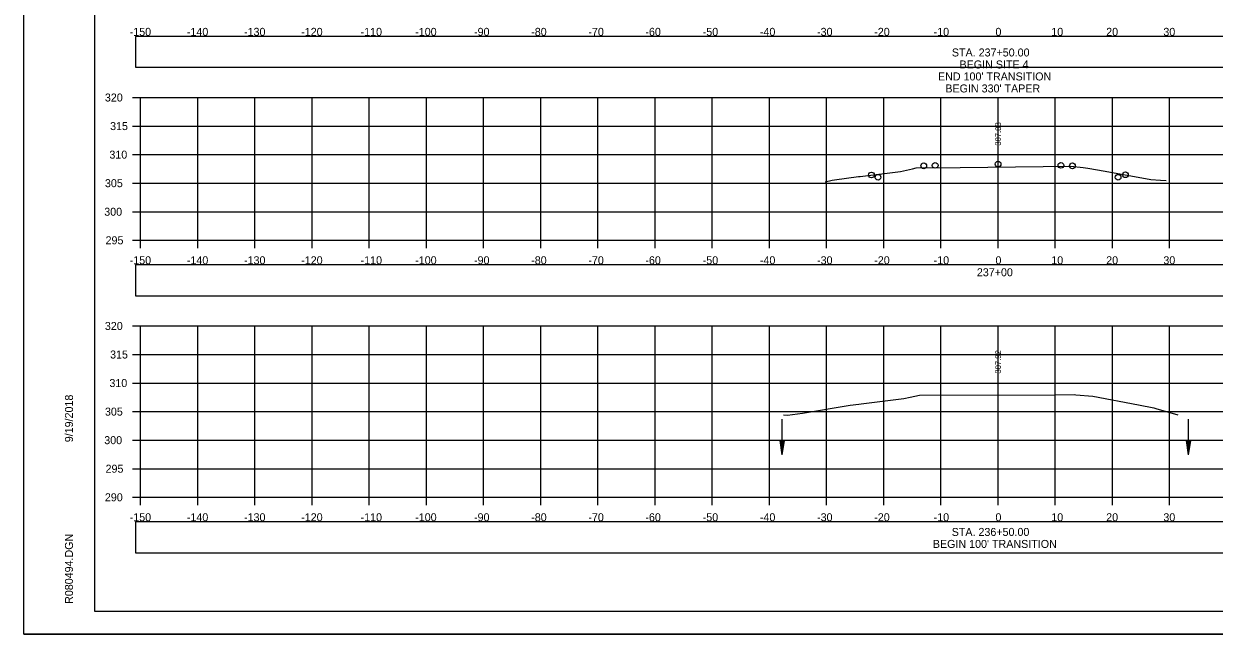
# Model space of a CAD drawing. Extents: x 1376273 to 1384221, y 378927 to 384592.
# Drawn here: x 1380387.4 to 1380595.6, y 379685.2 to 379792.1 of the extents above; entities that cross this region are included whole.
import ezdxf

# ---------------------------------------------------------------- set-up
doc = ezdxf.new("R2010")
doc.units = 0
for name, color, linetype in [('R_Axis', 7, 'Continuous'), ('R_Axis Annot', 7, 'Continuous'), ('R_Border', 7, 'Continuous'), ('R_Exist Surface', 7, 'Continuous'), ('R_Grid', 7, 'Continuous'), ('R_No Plot', 7, 'Continuous'), ('R_Water', 7, 'Continuous'), ('R_Xsect Elev', 7, 'Continuous')]:
    doc.layers.add(name, color=color, linetype=linetype)

msp = doc.modelspace()

# ---------------------------------------------------------------- linework, layer by layer
at = {"layer": 'R_Axis'}
for p, q in [((1380406.44, 379779.14), (1380407.84, 379779.14)), ((1380407.84, 379754.14), (1380407.84, 379779.14)), ((1380406.44, 379774.14), (1380407.84, 379774.14)), ((1380406.44, 379769.14), (1380407.84, 379769.14)), ((1380406.44, 379764.14), (1380407.84, 379764.14)), ((1380406.44, 379759.14), (1380407.84, 379759.14)), ((1380406.44, 379754.14), (1380407.84, 379754.14)), ((1380407.84, 379754.14), (1380707.84, 379754.14)), ((1380407.84, 379752.74), (1380407.84, 379754.14)), ((1380417.84, 379752.74), (1380417.84, 379754.14)), ((1380427.84, 379752.74), (1380427.84, 379754.14)), ((1380437.84, 379752.74), (1380437.84, 379754.14)), ((1380447.84, 379752.74), (1380447.84, 379754.14)), ((1380457.84, 379752.74), (1380457.84, 379754.14)), ((1380467.84, 379752.74), (1380467.84, 379754.14)), ((1380477.84, 379752.74), (1380477.84, 379754.14)), ((1380487.84, 379752.74), (1380487.84, 379754.14)), ((1380497.84, 379752.74), (1380497.84, 379754.14)), ((1380507.84, 379752.74), (1380507.84, 379754.14)), ((1380517.84, 379752.74), (1380517.84, 379754.14)), ((1380527.84, 379752.74), (1380527.84, 379754.14)), ((1380537.84, 379752.74), (1380537.84, 379754.14)), ((1380547.84, 379752.74), (1380547.84, 379754.14)), ((1380557.84, 379752.74), (1380557.84, 379754.14)), ((1380567.84, 379752.74), (1380567.84, 379754.14)), ((1380577.84, 379752.74), (1380577.84, 379754.14)), ((1380587.84, 379752.74), (1380587.84, 379754.14)), ((1380406.44, 379739.14), (1380407.84, 379739.14)), ((1380407.84, 379709.14), (1380407.84, 379739.14)), ((1380406.44, 379734.14), (1380407.84, 379734.14)), ((1380406.44, 379729.14), (1380407.84, 379729.14)), ((1380406.44, 379724.14), (1380407.84, 379724.14)), ((1380406.44, 379719.14), (1380407.84, 379719.14)), ((1380406.44, 379714.14), (1380407.84, 379714.14)), ((1380406.44, 379709.14), (1380407.84, 379709.14)), ((1380407.84, 379709.14), (1380707.84, 379709.14)), ((1380407.84, 379707.74), (1380407.84, 379709.14)), ((1380417.84, 379707.74), (1380417.84, 379709.14)), ((1380427.84, 379707.74), (1380427.84, 379709.14)), ((1380437.84, 379707.74), (1380437.84, 379709.14)), ((1380447.84, 379707.74), (1380447.84, 379709.14)), ((1380457.84, 379707.74), (1380457.84, 379709.14)), ((1380467.84, 379707.74), (1380467.84, 379709.14)), ((1380477.84, 379707.74), (1380477.84, 379709.14)), ((1380487.84, 379707.74), (1380487.84, 379709.14)), ((1380497.84, 379707.74), (1380497.84, 379709.14)), ((1380507.84, 379707.74), (1380507.84, 379709.14)), ((1380517.84, 379707.74), (1380517.84, 379709.14)), ((1380527.84, 379707.74), (1380527.84, 379709.14)), ((1380537.84, 379707.74), (1380537.84, 379709.14)), ((1380547.84, 379707.74), (1380547.84, 379709.14)), ((1380557.84, 379707.74), (1380557.84, 379709.14)), ((1380567.84, 379707.74), (1380567.84, 379709.14)), ((1380577.84, 379707.74), (1380577.84, 379709.14)), ((1380587.84, 379707.74), (1380587.84, 379709.14))]:
    msp.add_line(p, q, dxfattribs=at)
at = {"layer": 'R_Axis Annot'}
for points in [[(1380406.97, 379784.44), (1380708.66, 379784.44), (1380708.66, 379789.85), (1380406.97, 379789.85)], [(1380406.97, 379744.43), (1380708.66, 379744.43), (1380708.66, 379749.84), (1380406.97, 379749.84)], [(1380406.97, 379699.42), (1380708.66, 379699.42), (1380708.66, 379704.83), (1380406.97, 379704.83)]]:
    msp.add_lwpolyline(points, close=True, dxfattribs=at)
at = {"layer": 'R_Border'}
for p, q in [((1380399.84, 379689.14), (1380399.84, 379894.6)), ((1380399.84, 379689.14), (1380399.84, 379689.14)), ((1380716.02, 379689.14), (1380399.84, 379689.14))]:
    msp.add_line(p, q, dxfattribs=at)
at = {"layer": 'R_Exist Surface'}
for points in [[(1380527.61, 379764.35), (1380528.82, 379764.65), (1380529.22, 379764.71), (1380533.42, 379765.29), (1380533.53, 379765.3), (1380533.74, 379765.33), (1380540.79, 379766.21), (1380542.86, 379766.68), (1380543.52, 379766.83), (1380551.21, 379766.9), (1380570.59, 379767.11), (1380572.75, 379766.86), (1380573.52, 379766.78), (1380576.59, 379766.23), (1380584.56, 379764.81), (1380586.27, 379764.69), (1380587.25, 379764.63)], [(1380520.29, 379723.55), (1380521.01, 379723.51), (1380523.65, 379723.84), (1380531.97, 379725.26), (1380533.5, 379725.47), (1380533.89, 379725.52), (1380541.38, 379726.45), (1380542.44, 379726.67), (1380544.1, 379727.01), (1380567.91, 379727.1), (1380571.16, 379727.12), (1380571.43, 379727.1), (1380574.43, 379726.85), (1380582.43, 379725.33), (1380585.07, 379724.83), (1380585.45, 379724.71), (1380589.3, 379723.55)]]:
    msp.add_lwpolyline(points, dxfattribs=at)
at = {"layer": 'R_Grid'}
for p, q in [((1380407.84, 379779.14), (1380707.84, 379779.14)), ((1380407.84, 379754.14), (1380407.84, 379779.14)), ((1380417.84, 379754.14), (1380417.84, 379779.14)), ((1380427.84, 379754.14), (1380427.84, 379779.14)), ((1380437.84, 379754.14), (1380437.84, 379779.14)), ((1380447.84, 379754.14), (1380447.84, 379779.14)), ((1380457.84, 379754.14), (1380457.84, 379779.14)), ((1380467.84, 379754.14), (1380467.84, 379779.14)), ((1380477.84, 379754.14), (1380477.84, 379779.14)), ((1380487.84, 379754.14), (1380487.84, 379779.14)), ((1380497.84, 379754.14), (1380497.84, 379779.14)), ((1380507.84, 379754.14), (1380507.84, 379779.14)), ((1380517.84, 379754.14), (1380517.84, 379779.14)), ((1380527.84, 379754.14), (1380527.84, 379779.14)), ((1380537.84, 379754.14), (1380537.84, 379779.14)), ((1380547.84, 379754.14), (1380547.84, 379779.14)), ((1380557.84, 379754.14), (1380557.84, 379779.14)), ((1380567.84, 379754.14), (1380567.84, 379779.14)), ((1380577.84, 379754.14), (1380577.84, 379779.14)), ((1380587.84, 379754.14), (1380587.84, 379779.14)), ((1380407.84, 379774.14), (1380707.84, 379774.14)), ((1380407.84, 379769.14), (1380707.84, 379769.14)), ((1380407.84, 379764.14), (1380707.84, 379764.14)), ((1380407.84, 379759.14), (1380707.84, 379759.14)), ((1380407.84, 379754.14), (1380707.84, 379754.14)), ((1380407.84, 379739.14), (1380707.84, 379739.14)), ((1380407.84, 379709.14), (1380407.84, 379739.14)), ((1380417.84, 379709.14), (1380417.84, 379739.14)), ((1380427.84, 379709.14), (1380427.84, 379739.14)), ((1380437.84, 379709.14), (1380437.84, 379739.14)), ((1380447.84, 379709.14), (1380447.84, 379739.14)), ((1380457.84, 379709.14), (1380457.84, 379739.14)), ((1380467.84, 379709.14), (1380467.84, 379739.14)), ((1380477.84, 379709.14), (1380477.84, 379739.14)), ((1380487.84, 379709.14), (1380487.84, 379739.14)), ((1380497.84, 379709.14), (1380497.84, 379739.14)), ((1380507.84, 379709.14), (1380507.84, 379739.14)), ((1380517.84, 379709.14), (1380517.84, 379739.14)), ((1380527.84, 379709.14), (1380527.84, 379739.14)), ((1380537.84, 379709.14), (1380537.84, 379739.14)), ((1380547.84, 379709.14), (1380547.84, 379739.14)), ((1380557.84, 379709.14), (1380557.84, 379739.14)), ((1380567.84, 379709.14), (1380567.84, 379739.14)), ((1380577.84, 379709.14), (1380577.84, 379739.14)), ((1380587.84, 379709.14), (1380587.84, 379739.14)), ((1380407.84, 379734.14), (1380707.84, 379734.14)), ((1380407.84, 379729.14), (1380707.84, 379729.14)), ((1380407.84, 379724.14), (1380707.84, 379724.14)), ((1380407.84, 379719.14), (1380707.84, 379719.14)), ((1380407.84, 379714.14), (1380707.84, 379714.14)), ((1380407.84, 379709.14), (1380707.84, 379709.14))]:
    msp.add_line(p, q, dxfattribs=at)
at = {"layer": 'R_No Plot'}
msp.add_line((1380387.44, 379685.16), (1380720.77, 379685.16), dxfattribs=at)
for points in [[(1380387.43, 379898.5), (1380720.77, 379898.5), (1380720.77, 379685.16), (1380387.43, 379685.16)], [(1380633.76, 379894.6), (1380633.76, 379884.72), (1380669.49, 379884.72), (1380669.49, 379881.8), (1380692.69, 379881.8), (1380692.69, 379857.47), (1380716.02, 379857.47), (1380716.02, 379689.14), (1380399.84, 379689.14), (1380399.84, 379894.6)]]:
    msp.add_lwpolyline(points, close=True, dxfattribs=at)
for centre in [(1380544.84, 379767.18), (1380546.84, 379767.26), (1380557.84, 379767.48), (1380568.84, 379767.26), (1380570.84, 379767.18), (1380535.68, 379765.57), (1380536.84, 379765.18), (1380578.84, 379765.18), (1380580.11, 379765.61)]:
    msp.add_circle(centre, 0.5, dxfattribs=at)
at = {"layer": 'R_Water'}
for p, q in [((1380520.02, 379722.83), (1380520.02, 379716.58)), ((1380591.1, 379722.83), (1380591.1, 379716.58)), ((1380519.65, 379719.08), (1380520.02, 379716.58)), ((1380520.4, 379719.08), (1380519.65, 379719.08)), ((1380519.71, 379719.08), (1380520.02, 379716.99)), ((1380519.77, 379719.08), (1380520.02, 379717.42)), ((1380519.84, 379719.08), (1380520.02, 379717.84)), ((1380519.9, 379719.08), (1380520.02, 379718.26)), ((1380519.96, 379719.08), (1380520.02, 379718.68)), ((1380520.4, 379719.08), (1380520.02, 379716.58)), ((1380520.14, 379719.08), (1380520.02, 379718.26)), ((1380520.27, 379719.08), (1380520.02, 379717.42)), ((1380520.34, 379719.08), (1380520.02, 379716.99)), ((1380520.21, 379719.08), (1380520.02, 379717.84)), ((1380520.08, 379719.08), (1380520.02, 379718.68)), ((1380590.73, 379719.08), (1380591.1, 379716.58)), ((1380591.48, 379719.08), (1380590.73, 379719.08)), ((1380590.79, 379719.08), (1380591.1, 379716.99)), ((1380590.85, 379719.08), (1380591.1, 379717.42)), ((1380590.91, 379719.08), (1380591.1, 379717.84)), ((1380590.98, 379719.08), (1380591.1, 379718.26)), ((1380591.04, 379719.08), (1380591.1, 379718.68)), ((1380591.48, 379719.08), (1380591.1, 379716.58)), ((1380591.22, 379719.08), (1380591.1, 379718.26)), ((1380591.35, 379719.08), (1380591.1, 379717.42)), ((1380591.41, 379719.08), (1380591.1, 379716.99)), ((1380591.29, 379719.08), (1380591.1, 379717.84)), ((1380591.16, 379719.08), (1380591.1, 379718.68))]:
    msp.add_line(p, q, dxfattribs=at)

# ---------------------------------------------------------------- texts
at = {"layer": 'R_Axis Annot'}
for s, p in [('-150', (1380405.95, 379789.94)), ('-140', (1380415.95, 379789.94)), ('-130', (1380425.95, 379789.94)), ('-120', (1380435.95, 379789.94)), ('-110', (1380446.34, 379789.94)), ('-100', (1380455.89, 379789.94)), ('-90', (1380466.18, 379789.94)), ('-80', (1380476.18, 379789.94)), ('-70', (1380486.18, 379789.94)), ('-60', (1380496.15, 379789.94)), ('-50', (1380506.18, 379789.94)), ('-40', (1380516.18, 379789.94)), ('-30', (1380526.18, 379789.94)), ('-20', (1380536.18, 379789.94)), ('-10', (1380546.57, 379789.94)), ('0', (1380557.38, 379789.94)), ('10', (1380567.15, 379789.94)), ('20', (1380576.75, 379789.94)), ('30', (1380586.75, 379789.94)), ('STA. 237+50.00', (1380549.76, 379786.33)), ('BEGIN SITE 4', (1380551.1, 379784.23)), ("END 100' TRANSITION", (1380547.33, 379782.13)), ("BEGIN 330' TAPER", (1380548.62, 379780.03)), ('320', (1380401.61, 379778.44)), ('315', (1380402.52, 379773.44)), ('310', (1380402.4, 379768.44)), ('305', (1380401.62, 379763.44)), ('300', (1380401.5, 379758.44)), ('295', (1380401.73, 379753.44)), ('-150', (1380405.95, 379749.94)), ('-140', (1380415.95, 379749.94)), ('-130', (1380425.95, 379749.94)), ('-120', (1380435.95, 379749.94)), ('-110', (1380446.34, 379749.94)), ('-100', (1380455.89, 379749.94)), ('-90', (1380466.18, 379749.94)), ('-80', (1380476.18, 379749.94)), ('-70', (1380486.18, 379749.94)), ('-60', (1380496.15, 379749.94)), ('-50', (1380506.18, 379749.94)), ('-40', (1380516.18, 379749.94)), ('-30', (1380526.18, 379749.94)), ('-20', (1380536.18, 379749.94)), ('-10', (1380546.57, 379749.94)), ('0', (1380557.38, 379749.94)), ('10', (1380567.15, 379749.94)), ('20', (1380576.75, 379749.94)), ('30', (1380586.75, 379749.94)), ('237+00', (1380554.13, 379747.84)), ('320', (1380401.61, 379738.44)), ('315', (1380402.52, 379733.44)), ('310', (1380402.4, 379728.44)), ('305', (1380401.62, 379723.44)), ('300', (1380401.5, 379718.44)), ('295', (1380401.73, 379713.44)), ('290', (1380401.61, 379708.44)), ('-150', (1380405.95, 379704.94)), ('-140', (1380415.95, 379704.94)), ('-130', (1380425.95, 379704.94)), ('-120', (1380435.95, 379704.94)), ('-110', (1380446.34, 379704.94)), ('-100', (1380455.89, 379704.94)), ('-90', (1380466.18, 379704.94)), ('-80', (1380476.18, 379704.94)), ('-70', (1380486.18, 379704.94)), ('-60', (1380496.15, 379704.94)), ('-50', (1380506.18, 379704.94)), ('-40', (1380516.18, 379704.94)), ('-30', (1380526.18, 379704.94)), ('-20', (1380536.18, 379704.94)), ('-10', (1380546.57, 379704.94)), ('0', (1380557.38, 379704.94)), ('10', (1380567.15, 379704.94)), ('20', (1380576.75, 379704.94)), ('30', (1380586.75, 379704.94)), ('STA. 236+50.00', (1380549.73, 379702.37)), ("BEGIN 100' TRANSITION", (1380546.43, 379700.27))]:
    msp.add_text(s, height=1.4, dxfattribs=at).set_placement(p)
at = {"layer": 'R_Border'}
for s, p in [('9/19/2018', (1380396.03, 379718.78)), ('R080494.DGN', (1380396.03, 379690.47))]:
    msp.add_text(s, height=1.4, rotation=90, dxfattribs=at).set_placement(p)
at = {"layer": 'R_Xsect Elev'}
for s, p in [('307.83', (1380558.34, 379770.71)), ('307.92', (1380558.34, 379730.8))]:
    msp.add_text(s, height=1, rotation=90, dxfattribs=at).set_placement(p)

doc.saveas('drawing.dxf')
